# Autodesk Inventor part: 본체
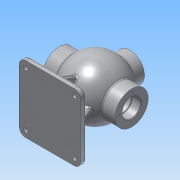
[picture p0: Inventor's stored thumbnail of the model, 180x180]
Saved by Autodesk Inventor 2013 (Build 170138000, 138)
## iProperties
Created: 2018-06
Part Number: 본체
Material: 알루미늄 6061
Document SubType Name: Modeling
Designer: Administrator
Density: 2.71 g/cm^3
Mass: 1509.58 g
Surface Area: 1153.86 cm^2
Volume: 557.04 cm^3
Author: Administrator
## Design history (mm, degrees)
sketch "스케치1"
  geometry: L1 (-68, 0)-(68, 0); L2 (68, 17.5)-(68, 31); L3 (-68, 31)-(-68, 17.5); L4 (68, 31)-(42.988, 31); L5 (-42.988, 31)-(-68, 31); L6 (-68, 17.5)-(-39.278, 17.5); L7 (50.25, 0)-(52, 0); L8 (52, 17.5)-(52, 18.5); L9 (52, 18.5)-(50.25, 18.5); L10 (50.25, 18.5)-(50.25, 17.5); L11 (39.278, 17.5)-(50.25, 17.5); L12 (52, 17.5)-(68, 17.5); A1 r 53 centre (0, 0) between (42.988, 31) and (-42.988, 31); A2 r 43 centre (0, 0) between (39.278, 17.5) and (-39.278, 17.5); 2 further points
  constraints: 24 end point, 5 parallel, 5 perpendicular, 4 point on circle, 4 vertical alignment, 3 coincident, 3 collinear, 2 centre point, 2 horizontal, 1 midpoint, 1 point on line
  dimensions: "d0" = 106 diameter of A1; "d4" = 31 distance of L1.end L2.end; "d5" = 86 diameter of A2; "d6" = 17.5 distance of L2.start L1.end; "d8" = 136 distance between parallel lines of L2 L3; "d9" = 1.75 distance of L8.end L9.end; "d10" = 16 distance between parallel lines of L2 L8; "d11" = 18.5 distance between parallel lines of L7 L9
revolve "회전1" sketch "스케치1" stored, may be unused: angle "d12" = 90 deg
sketch "스케치2"
  geometry: L1 (-57.5, -85)-(57.5, -85); L2 (57.5, -85)-(57.5, -75); L3 (57.5, -75)-(-57.5, -75); L4 (-57.5, -75)-(-57.5, -85); L5 (-57.5, -85)-(57.5, -75); L6 (57.5, -85)-(-57.5, -75); 3 further points
  constraints: 12 end point, 3 midpoint, 2 parallel, 1 horizontal, 1 perpendicular, 1 vertical alignment
  dimensions: "d13" = 115 distance of L3.end L2.end; "d14" = 10 distance of L2.end L1.end; "d15" = 85 distance from line of L1 point (0, 0)
extrude "돌출1" join sketch "스케치2" stored distance "d16" = 125; taper "d17" = 0 deg
fillet "모깎기1" dims "d18" = 12
node "작업 평면1"
sketch "스케치3"
  geometry: C1 r 27 at (0, 0); 1 further point
  constraints: 1 centre point, 1 coincident
  dimensions: "d20" = 54 diameter of C1
extrude "돌출2" join sketch "스케치3" stored distance "d21" = 115; taper "d22" = 0 deg
sketch "스케치5"
  geometry: 2 further points
  dimensions: "d25" = 45.5 horizontal distance of point (0, 113) point (45.5, 62.5); "d26" = 50.5 vertical distance of point (0, 113) point (45.5, 62.5)
hole "구멍1" sketch "스케치5" at (0, 113) diameter "d27" = 8; stored, may be unused: countersink angle "d31" = 90 deg, drill point angle "d33" = 118 deg; dims "d28" = 6, "d29" = 12, "d30" = 3, "d32" = 8
sketch "스케치6"
  geometry: C1 r 31 at (0, 0) reference; 1 further point
  constraints: 1 vertical alignment
  dimensions: "d34" = 22.5 distance of C1.centre point (0, 22.5)
hole "구멍2" sketch "스케치6" at (0, 22.5) diameter "d35" = 3.242; stored, may be unused: countersink angle "d39" = 90 deg, drill point angle "d41" = 118 deg; dims "d36" = 12, "d37" = 12, "d38" = 3, "d40" = 15
sketch "스케치7"
  geometry: C1 r 17.5 at (0, 0) reference; 1 further point
  constraints: 1 vertical alignment
  dimensions: "d45" = 24 distance of C1.centre point (0, 24)
hole "구멍3" sketch "스케치7" at (0, 24) diameter "d46" = 3.242; stored, may be unused: countersink angle "d50" = 90 deg, drill point angle "d52" = 118 deg; dims "d47" = 16, "d48" = 12, "d49" = 3, "d51" = 19
sketch "스케치8"
  geometry: C1 r 27 at (0, 0) reference; C2 r 13 at (0, 0)
  constraints: 1 centre point, 1 coincident
  dimensions: "d56" = 26 diameter of C2
extrude "돌출3" cut sketch "스케치8" stored distance "d57" = 115; taper "d58" = 0 deg
sketch "스케치9"
  geometry: C1 r 13 at (0, 0) reference; 1 further point
  constraints: 1 vertical alignment
  dimensions: "d59" = 20 distance of C1.centre point (0, 20)
hole "구멍4" sketch "스케치9" at (0, 20) diameter "d60" = 3.242; stored, may be unused: countersink angle "d64" = 90 deg, drill point angle "d66" = 118 deg; dims "d61" = 9, "d62" = 12, "d63" = 3, "d65" = 11
sketch "스케치10"
  geometry: L1 (0, 125)-(91, 125) reference; L2 (41.5, 10)-(49.5, 10); L3 (49.5, 10)-(49.5, 115); L4 (49.5, 115)-(41.5, 115); L5 (41.5, 115)-(41.5, 10); L6 (41.5, 10)-(49.5, 115); L7 (49.5, 10)-(41.5, 115); 1 further point
  constraints: 12 end point, 2 midpoint, 2 parallel, 1 horizontal, 1 perpendicular
  dimensions: "d70" = 8 distance of L4.end L3.end; "d71" = 10 distance between parallel lines of L1 L4
extrude "돌출5" join sketch "스케치10" stored distance "d76" = 115; taper "d77" = 0 deg
feature "면 기울기1" dims angle "d78" = 22 deg
sketch "스케치11"
  geometry: L1 (47.5, -75)-(42.22, -61.931); L2 (57.5, -75)-(57.5, -85) reference; L3 (39.5, -75)-(51.5, -75) reference; 1 further point
  constraints: 2 end point, 1 point on line
  dimensions: "d79" = 22 deg angle of L2 L1; "d80" = 10 distance of L2.start L1.start
feature "리브1" sketch "스케치11" dims "d81" = 1, "d82" = 8, "d83" = 0, "d84" = 0, "d85" = 1, "d86" = 1
node "작업 평면2"
fillet "모깎기2" dims "d92" = 3
fillet "모깎기4" dims "d94" = 3
chamfer "모따기1" distance "d95" = 1; stored, may be unused: second distance "d96" = 2, angle "d97" = 45 deg
sketch "스케치13"
  geometry: L1 (-27, 65)-(27, 65) reference; L2 (-27, 65)-(-27, 47.286) reference; 2 further points
  constraints: 1 other
  dimensions: "d98" = 10 distance from line of L1 point (0, 55); "d99" = 27 distance from line of L2 point (0, 55)
feature "엠보싱2" sketch "스케치13" dims "d0" = 106, "d4" = 31, "d5" = 86, "d6" = 17.5, "d8" = 136, "d9" = 1.75, "d10" = 16, "d11" = 18.5, "d13" = 115, "d14" = 10, "d15" = 85, "d100" = 0.5, "d101" = 0
node "솔리드1"
mirror "대칭1"
mirror "대칭2"
pattern_circular "원형 패턴1" dims angle "d43" = 360 deg
pattern_circular "원형 패턴2" dims angle "d54" = 360 deg
pattern_circular "원형 패턴3" dims angle "d68" = 360 deg
mirror "대칭3"
other parameters: "d19" = 65, "d87" = -27
